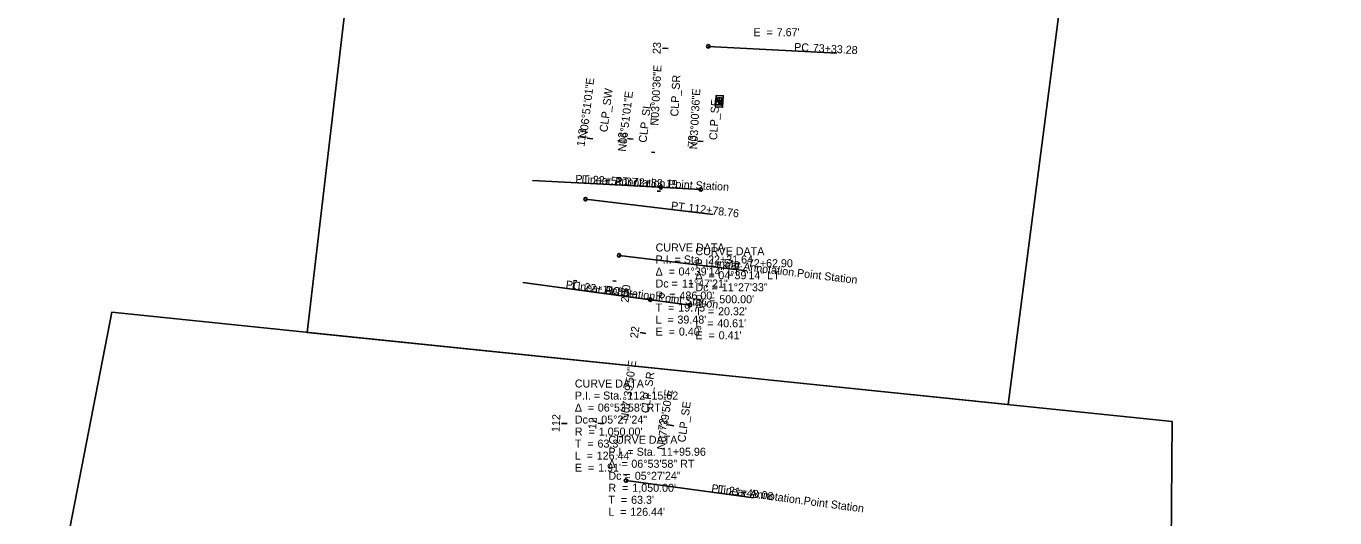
# Model space of a CAD drawing. Extents: x 1564517 to 1565226, y 635740 to 637455.
# Drawn here: x 1564587.2 to 1565045, y 636157.6 to 636329.5 of the extents above; entities that cross this region are included whole.
import ezdxf

# ---------------------------------------------------------------- set-up
doc = ezdxf.new("R2010")
doc.units = 0
for name, color, linetype in [('GK_Drainage_Nodes', 7, 'Continuous'), ('RD_P_Cells', 7, 'Continuous'), ('SC_Scratch10', 7, 'Continuous'), ('TX_P_1000', 7, 'Continuous'), ('UT_P_Water', 7, 'Continuous'), ('UT_P_Water_Cells', 7, 'Continuous'), ('UT_X_Electric', 7, 'Continuous'), ('UT_X_Sanitary_Pressure_Line', 7, 'Continuous'), ('UT_X_Water_Cells', 7, 'Continuous')]:
    doc.layers.add(name, color=color, linetype=linetype)

msp = doc.modelspace()

# ---------------------------------------------------------------- linework, layer by layer
at = {"layer": 'RD_P_Cells'}
msp.add_line((1564829.72, 636303.2), (1564829.72, 636303.2), dxfattribs=at)
msp.add_lwpolyline([(1564828.39, 636301.27), (1564828.61, 636305.26), (1564831.05, 636305.13), (1564830.83, 636301.13)], close=True, dxfattribs=at)
for points in [[(1564830.45, 636301.86), (1564828.85, 636301.95), (1564830.48, 636302.44), (1564828.91, 636303.08), (1564830.51, 636302.99)], [(1564829.71, 636304.22), (1564829.65, 636304.29), (1564829.61, 636304.33), (1564829.58, 636304.35), (1564829.55, 636304.37), (1564829.5, 636304.4), (1564829.47, 636304.41), (1564829.38, 636304.44), (1564829.34, 636304.44), (1564829.29, 636304.45), (1564829.22, 636304.44), (1564829.15, 636304.42), (1564829.1, 636304.38), (1564829.05, 636304.32), (1564829.02, 636304.27), (1564829, 636304.25), (1564828.98, 636304.19), (1564828.94, 636303.57), (1564830.54, 636303.48), (1564830.58, 636304.17), (1564830.53, 636304.26), (1564830.47, 636304.34), (1564830.38, 636304.41), (1564830.26, 636304.46), (1564830.15, 636304.48), (1564830.08, 636304.48), (1564830, 636304.46), (1564829.88, 636304.41), (1564829.8, 636304.36), (1564829.71, 636304.22), (1564829.67, 636303.53)]]:
    msp.add_lwpolyline(points, dxfattribs=at)
at = {"layer": 'TX_P_1000'}
for p, q in [((1564809.22, 636273.12), (1564764.28, 636275.49)), ((1564794.62, 636249.33), (1564839.3, 636243.97)), ((1564805.55, 636233.83), (1564760.95, 636239.83)), ((1564797.04, 636170.59), (1564841.64, 636164.59))]:
    msp.add_line(p, q, dxfattribs=at)
at = {"layer": 'UT_P_Water_Cells'}
for p, q in [((1564811.77, 636321.69), (1564810.57, 636321.75)), ((1564825.83, 636322.41), (1564870.77, 636320.05)), ((1564785.42, 636290.07), (1564784.22, 636290.21)), ((1564799.5, 636289.94), (1564798.31, 636290.08)), ((1564824.08, 636289.17), (1564822.88, 636289.23)), ((1564809.22, 636273.12), (1564764.28, 636275.49)), ((1564823.2, 636272.39), (1564778.26, 636274.75)), ((1564782.88, 636268.98), (1564827.56, 636263.62)), ((1564794.62, 636249.33), (1564839.3, 636243.97)), ((1564805.55, 636233.83), (1564760.95, 636239.83)), ((1564819.42, 636231.96), (1564774.82, 636237.96)), ((1564800.84, 636235.64), (1564798.85, 636235.87)), ((1564803.96, 636222.04), (1564802.77, 636222.2)), ((1564776.43, 636190.5), (1564775.23, 636190.56)), ((1564789.23, 636190.49), (1564788.03, 636190.56)), ((1564813.74, 636189.76), (1564812.56, 636189.92)), ((1564797.04, 636170.59), (1564841.64, 636164.59))]:
    msp.add_line(p, q, dxfattribs=at)
for centre in [(1564825.83, 636322.41), (1564809.22, 636273.12), (1564823.2, 636272.39), (1564782.88, 636268.98), (1564794.62, 636249.33), (1564805.55, 636233.83), (1564819.42, 636231.96), (1564797.04, 636170.59)]:
    msp.add_circle(centre, 0.6, dxfattribs=at)
at = {"layer": 'UT_X_Electric'}
for points in [[(1564685.49, 636222.38), (1564930.72, 636197.15), (1564955.53, 636388.56), (1565013.42, 636482), (1565045.03, 636594.7), (1564968.04, 636598.47), (1565001.39, 636689.39), (1564864.83, 636740.08), (1564842.01, 636748.56), (1564682.06, 636752.05), (1564649.71, 636425.72), (1564708.41, 636418.15)], [(1564658.34, 635750.59), (1564898, 635751.43), (1564898, 635751.43), (1564898, 635751.43), (1564956.75, 635750.68), (1564987.45, 635750.7), (1564987.39, 635815.7), (1564987.33, 635880.7), (1564987.28, 635945.7), (1564987.22, 636010.7), (1564987.17, 636075.7), (1564988.09, 636191.25), (1564617.12, 636229.41), (1564587.17, 636075.36), (1564587.22, 636010.36), (1564660.39, 635967.97), (1564659.6, 635859.64), (1564658.34, 635750.59), (1564658.34, 635750.59)]]:
    msp.add_lwpolyline(points, close=True, dxfattribs=at)
at = {"layer": 'UT_X_Sanitary_Pressure_Line'}
for p, q in [((1564825.83, 636322.41), (1564870.77, 636320.05)), ((1564809.22, 636273.12), (1564764.28, 636275.49)), ((1564823.2, 636272.39), (1564778.26, 636274.75)), ((1564782.88, 636268.98), (1564827.56, 636263.62)), ((1564794.62, 636249.33), (1564839.3, 636243.97)), ((1564805.55, 636233.83), (1564760.95, 636239.83)), ((1564819.42, 636231.96), (1564774.82, 636237.96)), ((1564800.84, 636235.64), (1564798.85, 636235.87)), ((1564797.04, 636170.59), (1564841.64, 636164.59))]:
    msp.add_line(p, q, dxfattribs=at)
for centre in [(1564825.83, 636322.41), (1564809.22, 636273.12), (1564823.2, 636272.39), (1564782.88, 636268.98), (1564794.62, 636249.33), (1564805.55, 636233.83), (1564819.42, 636231.96), (1564797.04, 636170.59)]:
    msp.add_circle(centre, 0.6, dxfattribs=at)
at = {"layer": 'UT_X_Water_Cells'}
for p, q in [((1564811.77, 636321.69), (1564809.78, 636321.79)), ((1564785.42, 636290.07), (1564783.43, 636290.31)), ((1564799.5, 636289.94), (1564797.51, 636290.18)), ((1564824.08, 636289.17), (1564822.08, 636289.28)), ((1564807.15, 636285.24), (1564805.96, 636285.41)), ((1564809.15, 636271.76), (1564807.95, 636271.82)), ((1564779.84, 636240.38), (1564778.65, 636240.49)), ((1564793.58, 636240.29), (1564792.38, 636240.42)), ((1564820.36, 636239.32), (1564819.17, 636239.46)), ((1564800.84, 636235.64), (1564798.85, 636235.87)), ((1564803.96, 636222.04), (1564801.98, 636222.31)), ((1564776.43, 636190.5), (1564774.43, 636190.59)), ((1564789.23, 636190.49), (1564787.23, 636190.61)), ((1564795.72, 636185.91), (1564794.53, 636186.02)), ((1564813.74, 636189.76), (1564811.76, 636190.03)), ((1564797.29, 636172.49), (1564796.1, 636172.65))]:
    msp.add_line(p, q, dxfattribs=at)
msp.add_circle((1564797.04, 636170.59), 0.6, dxfattribs=at)

# ---------------------------------------------------------------- texts
at = {"layer": 'GK_Drainage_Nodes'}
for s, p in [('E  = ', (1564841.6, 636325.95)), ("7.67'", (1564849.76, 636325.95)), ('CURVE DATA', (1564807.38, 636250.68)), ('CURVE DATA', (1564821.31, 636249.38)), ('P.I. = Sta. ', (1564807.38, 636246.48)), ('P.I. = Sta. ', (1564821.31, 636245.18)), ('22+31.64', (1564825.75, 636246.48)), ('72+62.90', (1564839.68, 636245.18)), ('Δ  = ', (1564807.38, 636242.28)), ('Dc = ', (1564807.38, 636238.08)), ('04°39\'14" LT', (1564815.41, 636242.28)), ('11°47\'21"', (1564816.62, 636238.08)), ('Δ  = ', (1564821.31, 636240.98)), ('04°39\'14" LT', (1564829.33, 636240.98)), ('R  = ', (1564807.38, 636233.88)), ("486.00'", (1564815.75, 636233.88)), ('Dc = ', (1564821.31, 636236.78)), ('11°27\'33"', (1564830.55, 636236.78)), ('T  = ', (1564807.38, 636229.68)), ("19.75'", (1564815.32, 636229.68)), ('R  = ', (1564821.31, 636232.58)), ("500.00'", (1564829.68, 636232.58)), ('L  = ', (1564807.38, 636225.48)), ("39.48'", (1564815.03, 636225.48)), ('T  = ', (1564821.31, 636228.38)), ("20.32'", (1564829.24, 636228.38)), ('E  = ', (1564807.38, 636221.28)), ("0.40'", (1564815.54, 636221.28)), ('L  = ', (1564821.31, 636224.18)), ('E  = ', (1564821.31, 636219.98)), ("40.61'", (1564828.96, 636224.18)), ("0.41'", (1564829.46, 636219.98)), ('CURVE DATA', (1564779.13, 636203.11)), ('P.I. = Sta. ', (1564779.13, 636198.91)), ('112+15.62', (1564797.5, 636198.91)), ('Δ  = ', (1564779.13, 636194.71)), ('06°53\'58" RT', (1564787.16, 636194.71)), ('Dc = ', (1564779.13, 636190.51)), ('05°27\'24"', (1564788.37, 636190.51)), ('R  = ', (1564779.13, 636186.31)), ("1,050.00'", (1564787.5, 636186.31)), ('CURVE DATA', (1564790.87, 636183.46)), ('T  = ', (1564779.13, 636182.11)), ("63.3'", (1564787.07, 636182.11)), ('P.I. = Sta. ', (1564790.87, 636179.26)), ('11+95.96', (1564809.24, 636179.26)), ('L  = ', (1564779.13, 636177.91)), ("126.44'", (1564786.78, 636177.91)), ('Δ  = ', (1564790.87, 636175.06)), ('06°53\'58" RT', (1564798.9, 636175.06)), ('E  = ', (1564779.13, 636173.71)), ("1.91'", (1564787.29, 636173.71)), ('Dc = ', (1564790.87, 636170.86)), ('05°27\'24"', (1564800.11, 636170.86)), ('R  = ', (1564790.87, 636166.66)), ("1,050.00'", (1564799.24, 636166.66)), ('T  = ', (1564790.87, 636162.46)), ("63.3'", (1564798.81, 636162.46)), ('L  = ', (1564790.87, 636158.26)), ("126.44'", (1564798.52, 636158.26))]:
    msp.add_text(s, height=2.8, dxfattribs=at).set_placement(p)
for s, rotation, p in [('N03°00\'36"E', 86.99, (1564808.35, 636294.63)), ('N06°51\'01"E', 83.1496, (1564783.42, 636290.19)), ('CLP_SR', 86.99, (1564815.32, 636297.83)), ('CLP_SW', 83.1496, (1564790.51, 636292.27)), ('N06°51\'01"E', 83.1496, (1564796.95, 636285.48)), ('N03°00\'36"E', 86.99, (1564821.93, 636286.34)), ('CLP_SL', 83.1496, (1564804.17, 636288.6)), ('CLP_SE', 86.99, (1564828.91, 636289.57)), ('N07°39\'50"E', 82.3361, (1564797.82, 636191.39)), ('CLP_SR', 82.3361, (1564805.03, 636194.01)), ('N07°39\'50"E', 82.3361, (1564810.57, 636181.17)), ('CLP_SE', 82.3361, (1564817.79, 636183.82))]:
    msp.add_text(s, height=2.8, rotation=rotation, dxfattribs=at).set_placement(p)
at = {"layer": 'SC_Scratch10'}
for s, p in [('E  = ', (1564841.6, 636325.95)), ("7.67'", (1564849.76, 636325.95)), ('CURVE DATA', (1564807.38, 636250.68)), ('CURVE DATA', (1564821.31, 636249.38)), ('P.I. = Sta. ', (1564807.38, 636246.48)), ('P.I. = Sta. ', (1564821.31, 636245.18)), ('22+31.64', (1564825.75, 636246.48)), ('72+62.90', (1564839.68, 636245.18)), ('Δ  = ', (1564807.38, 636242.28)), ('Dc = ', (1564807.38, 636238.08)), ('04°39\'14" LT', (1564815.41, 636242.28)), ('11°47\'21"', (1564816.62, 636238.08)), ('Δ  = ', (1564821.31, 636240.98)), ('04°39\'14" LT', (1564829.33, 636240.98)), ('R  = ', (1564807.38, 636233.88)), ("486.00'", (1564815.75, 636233.88)), ('Dc = ', (1564821.31, 636236.78)), ('11°27\'33"', (1564830.55, 636236.78)), ('T  = ', (1564807.38, 636229.68)), ("19.75'", (1564815.32, 636229.68)), ('R  = ', (1564821.31, 636232.58)), ("500.00'", (1564829.68, 636232.58)), ('L  = ', (1564807.38, 636225.48)), ("39.48'", (1564815.03, 636225.48)), ('T  = ', (1564821.31, 636228.38)), ("20.32'", (1564829.24, 636228.38)), ('E  = ', (1564807.38, 636221.28)), ("0.40'", (1564815.54, 636221.28)), ('L  = ', (1564821.31, 636224.18)), ('E  = ', (1564821.31, 636219.98)), ("40.61'", (1564828.96, 636224.18)), ("0.41'", (1564829.46, 636219.98)), ('CURVE DATA', (1564779.13, 636203.11)), ('P.I. = Sta. ', (1564779.13, 636198.91)), ('112+15.62', (1564797.5, 636198.91)), ('Δ  = ', (1564779.13, 636194.71)), ('06°53\'58" RT', (1564787.16, 636194.71)), ('Dc = ', (1564779.13, 636190.51)), ('05°27\'24"', (1564788.37, 636190.51)), ('R  = ', (1564779.13, 636186.31)), ("1,050.00'", (1564787.5, 636186.31)), ('CURVE DATA', (1564790.87, 636183.46)), ('T  = ', (1564779.13, 636182.11)), ("63.3'", (1564787.07, 636182.11)), ('P.I. = Sta. ', (1564790.87, 636179.26)), ('11+95.96', (1564809.24, 636179.26)), ('L  = ', (1564779.13, 636177.91)), ("126.44'", (1564786.78, 636177.91)), ('Δ  = ', (1564790.87, 636175.06)), ('06°53\'58" RT', (1564798.9, 636175.06)), ('E  = ', (1564779.13, 636173.71)), ("1.91'", (1564787.29, 636173.71)), ('Dc = ', (1564790.87, 636170.86)), ('05°27\'24"', (1564800.11, 636170.86)), ('R  = ', (1564790.87, 636166.66)), ("1,050.00'", (1564799.24, 636166.66)), ('T  = ', (1564790.87, 636162.46)), ("63.3'", (1564798.81, 636162.46)), ('L  = ', (1564790.87, 636158.26)), ("126.44'", (1564798.52, 636158.26))]:
    msp.add_text(s, height=2.8, dxfattribs=at).set_placement(p)
for s, rotation, p in [('N03°00\'36"E', 86.99, (1564808.35, 636294.63)), ('N06°51\'01"E', 83.1496, (1564783.42, 636290.19)), ('CLP_SR', 86.99, (1564815.32, 636297.83)), ('CLP_SW', 83.1496, (1564790.51, 636292.27)), ('N06°51\'01"E', 83.1496, (1564796.95, 636285.48)), ('N03°00\'36"E', 86.99, (1564821.93, 636286.34)), ('CLP_SL', 83.1496, (1564804.17, 636288.6)), ('CLP_SE', 86.99, (1564828.91, 636289.57)), ('N07°39\'50"E', 82.3361, (1564797.82, 636191.39)), ('CLP_SR', 82.3361, (1564805.03, 636194.01)), ('N07°39\'50"E', 82.3361, (1564810.57, 636181.17)), ('CLP_SE', 82.3361, (1564817.79, 636183.82))]:
    msp.add_text(s, height=2.8, rotation=rotation, dxfattribs=at).set_placement(p)
at = {"layer": 'TX_P_1000'}
for rotation, p in [(356.99, (1564781.43, 636274.58)), (353.1496, (1564826.57, 636245.5)), (352.3361, (1564777.97, 636237.54)), (352.3361, (1564828.92, 636166.3))]:
    msp.add_text('Linear Annotation.Point Station', height=2.8, rotation=rotation, dxfattribs=at).set_placement(p)
at = {"layer": 'UT_P_Water'}
for s, p in [('E  = ', (1564841.6, 636325.95)), ("7.67'", (1564849.76, 636325.95)), ('CURVE DATA', (1564807.38, 636250.68)), ('CURVE DATA', (1564821.31, 636249.38)), ('P.I. = Sta. ', (1564807.38, 636246.48)), ('P.I. = Sta. ', (1564821.31, 636245.18)), ('22+31.64', (1564825.75, 636246.48)), ('72+62.90', (1564839.68, 636245.18)), ('Δ  = ', (1564807.38, 636242.28)), ('Dc = ', (1564807.38, 636238.08)), ('04°39\'14" LT', (1564815.41, 636242.28)), ('11°47\'21"', (1564816.62, 636238.08)), ('Δ  = ', (1564821.31, 636240.98)), ('04°39\'14" LT', (1564829.33, 636240.98)), ('R  = ', (1564807.38, 636233.88)), ("486.00'", (1564815.75, 636233.88)), ('Dc = ', (1564821.31, 636236.78)), ('11°27\'33"', (1564830.55, 636236.78)), ('T  = ', (1564807.38, 636229.68)), ("19.75'", (1564815.32, 636229.68)), ('R  = ', (1564821.31, 636232.58)), ("500.00'", (1564829.68, 636232.58)), ('L  = ', (1564807.38, 636225.48)), ("39.48'", (1564815.03, 636225.48)), ('T  = ', (1564821.31, 636228.38)), ("20.32'", (1564829.24, 636228.38)), ('E  = ', (1564807.38, 636221.28)), ("0.40'", (1564815.54, 636221.28)), ('L  = ', (1564821.31, 636224.18)), ('E  = ', (1564821.31, 636219.98)), ("40.61'", (1564828.96, 636224.18)), ("0.41'", (1564829.46, 636219.98)), ('CURVE DATA', (1564779.13, 636203.11)), ('P.I. = Sta. ', (1564779.13, 636198.91)), ('112+15.62', (1564797.5, 636198.91)), ('Δ  = ', (1564779.13, 636194.71)), ('06°53\'58" RT', (1564787.16, 636194.71)), ('Dc = ', (1564779.13, 636190.51)), ('05°27\'24"', (1564788.37, 636190.51)), ('R  = ', (1564779.13, 636186.31)), ("1,050.00'", (1564787.5, 636186.31)), ('CURVE DATA', (1564790.87, 636183.46)), ('T  = ', (1564779.13, 636182.11)), ("63.3'", (1564787.07, 636182.11)), ('P.I. = Sta. ', (1564790.87, 636179.26)), ('11+95.96', (1564809.24, 636179.26)), ('L  = ', (1564779.13, 636177.91)), ("126.44'", (1564786.78, 636177.91)), ('Δ  = ', (1564790.87, 636175.06)), ('06°53\'58" RT', (1564798.9, 636175.06)), ('E  = ', (1564779.13, 636173.71)), ("1.91'", (1564787.29, 636173.71)), ('Dc = ', (1564790.87, 636170.86)), ('05°27\'24"', (1564800.11, 636170.86)), ('R  = ', (1564790.87, 636166.66)), ("1,050.00'", (1564799.24, 636166.66)), ('T  = ', (1564790.87, 636162.46)), ("63.3'", (1564798.81, 636162.46)), ('L  = ', (1564790.87, 636158.26)), ("126.44'", (1564798.52, 636158.26))]:
    msp.add_text(s, height=2.8, dxfattribs=at).set_placement(p)
for s, rotation, p in [('N03°00\'36"E', 86.99, (1564808.35, 636294.63)), ('N06°51\'01"E', 83.1496, (1564783.42, 636290.19)), ('CLP_SR', 86.99, (1564815.32, 636297.83)), ('CLP_SW', 83.1496, (1564790.51, 636292.27)), ('N06°51\'01"E', 83.1496, (1564796.95, 636285.48)), ('N03°00\'36"E', 86.99, (1564821.93, 636286.34)), ('CLP_SL', 83.1496, (1564804.17, 636288.6)), ('CLP_SE', 86.99, (1564828.91, 636289.57)), ('N07°39\'50"E', 82.3361, (1564797.82, 636191.39)), ('CLP_SR', 82.3361, (1564805.03, 636194.01)), ('N07°39\'50"E', 82.3361, (1564810.57, 636181.17)), ('CLP_SE', 82.3361, (1564817.79, 636183.82))]:
    msp.add_text(s, height=2.8, rotation=rotation, dxfattribs=at).set_placement(p)
at = {"layer": 'UT_P_Water_Cells'}
for s, rotation, p in [('PC', 356.99, (1564855.79, 636320.83)), ('73+33.28', 356.99, (1564862.3, 636320.49)), ('PT', 356.99, (1564779.26, 636274.7)), ('22+51.37', 356.99, (1564785.34, 636274.38)), ('PT', 356.99, (1564793.24, 636273.96)), ('72+83.19', 356.99, (1564799.32, 636273.64)), ('PT', 353.1496, (1564812.67, 636265.41)), ('112+78.76', 353.1496, (1564818.71, 636264.68)), ('PT', 353.1496, (1564824.41, 636245.75)), ('12+59.10', 353.1496, (1564830.45, 636245.03)), ('PC', 352.3361, (1564775.82, 636237.83)), ('22+11.89', 352.3361, (1564782.28, 636236.96)), ('PC', 352.3361, (1564789.69, 636235.96)), ('200', 83.4365, (1564797.93, 636232.68)), ('72+42.58', 352.3361, (1564796.15, 636235.09)), ('PT', 352.3361, (1564826.77, 636166.59)), ('21+48.08', 352.3361, (1564832.8, 636165.78))]:
    msp.add_text(s, height=2.8, rotation=rotation, dxfattribs=at).set_placement(p)
at = {"layer": 'UT_X_Sanitary_Pressure_Line'}
for s, rotation, p in [('PC', 356.99, (1564855.79, 636320.83)), ('73+33.28', 356.99, (1564862.3, 636320.49)), ('PT', 356.99, (1564779.26, 636274.7)), ('22+51.37', 356.99, (1564785.34, 636274.38)), ('PT', 356.99, (1564793.24, 636273.96)), ('72+83.19', 356.99, (1564799.32, 636273.64)), ('PT', 353.1496, (1564812.67, 636265.41)), ('112+78.76', 353.1496, (1564818.71, 636264.68)), ('PT', 353.1496, (1564824.41, 636245.75)), ('12+59.10', 353.1496, (1564830.45, 636245.03)), ('PC', 352.3361, (1564775.82, 636237.83)), ('22+11.89', 352.3361, (1564782.28, 636236.96)), ('PC', 352.3361, (1564789.69, 636235.96)), ('200', 83.4365, (1564797.93, 636232.68)), ('72+42.58', 352.3361, (1564796.15, 636235.09)), ('PT', 352.3361, (1564826.77, 636166.59)), ('21+48.08', 352.3361, (1564832.8, 636165.78))]:
    msp.add_text(s, height=2.8, rotation=rotation, dxfattribs=at).set_placement(p)
at = {"layer": 'UT_X_Water_Cells'}
for s, rotation, p in [('23', 86.99, (1564809.11, 636319.65)), ('113', 83.1496, (1564782.51, 636287.28)), ('13', 83.1496, (1564796.71, 636288.08)), ('73', 86.99, (1564821.42, 636287.13)), ('200', 83.4365, (1564797.93, 636232.68)), ('22', 82.3361, (1564801.19, 636220.21)), ('112', 87.4475, (1564773.79, 636187.49)), ('12', 86.3747, (1564786.59, 636188.46)), ('72', 82.3361, (1564810.98, 636187.93))]:
    msp.add_text(s, height=2.8, rotation=rotation, dxfattribs=at).set_placement(p)

doc.saveas('drawing.dxf')
